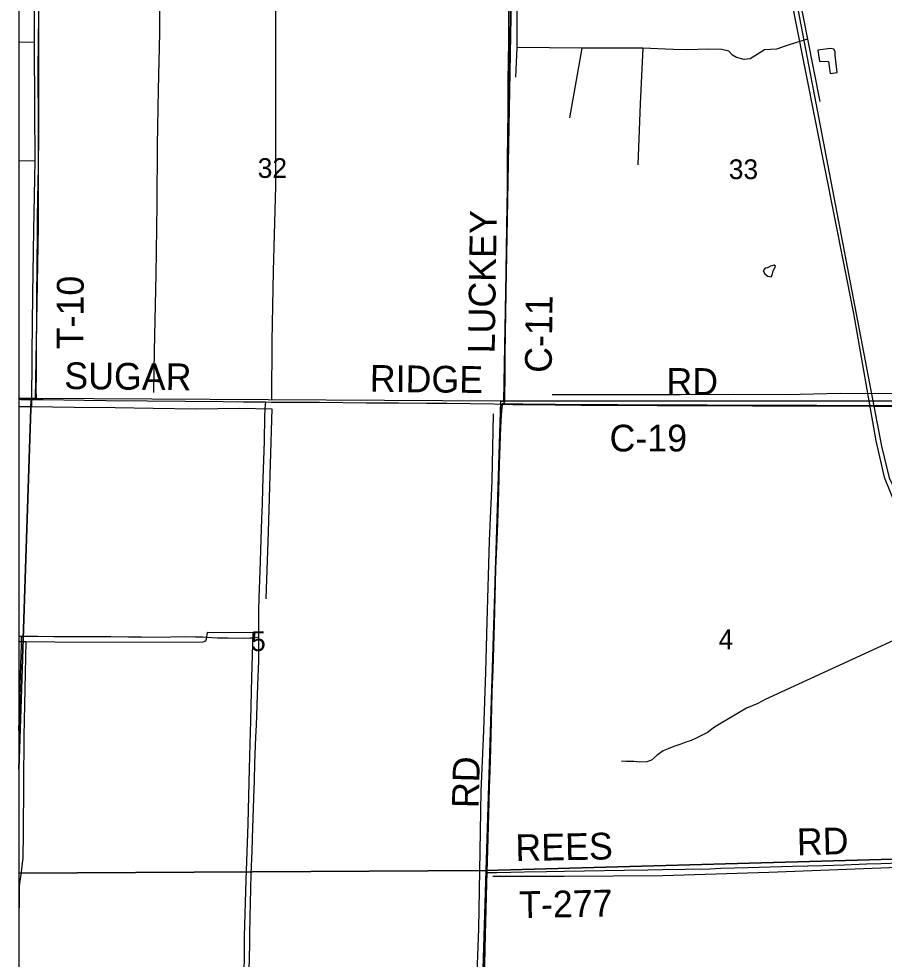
# Model space of a CAD drawing. Extents: x 0 to 34, y 0 to 22.
# Drawn here: x 2.1 to 3.939, y 17.332 to 19.331 of the extents above; entities that cross this region are included whole.
import ezdxf

# ---------------------------------------------------------------- set-up
doc = ezdxf.new("R2010")
doc.units = 0
for name, color, linetype in [('Default', 7, 'Continuous'), ('GM_X_County_Road', 7, 'Continuous'), ('GM_X_County_Road_Text', 7, 'Continuous'), ('GM_X_Minor_Lake', 7, 'Continuous'), ('GM_X_Minor_River', 7, 'Continuous'), ('GM_X_Rail_Line', 7, 'Continuous'), ('GM_X_Section', 7, 'Continuous'), ('GM_X_Section_Text', 7, 'Continuous'), ('GM_X_Township_Road', 7, 'Continuous'), ('GM_X_Township_Road_Text', 7, 'Continuous'), ('SH_Cut_Line', 7, 'Continuous'), ('SH_Data', 7, 'Continuous')]:
    doc.layers.add(name, color=color, linetype=linetype)

msp = doc.modelspace()

# ---------------------------------------------------------------- linework, layer by layer
at = {"layer": 'Default'}
for points in [[(2.1, 20.9), (2.1, 15.5125)], [(3.0884, 17.2887), (3.0911, 17.385), (3.094, 17.4937), (3.0947, 17.5172), (3.096, 17.5652), (3.0979, 17.6397), (3.0996, 17.6956), (3.1006, 17.7329), (3.102, 17.7795), (3.1045, 17.8665), (3.1053, 17.9007), (3.1069, 17.9473), (3.1096, 18.0436), (3.1115, 18.1026), (3.1131, 18.1616), (3.1153, 18.224), (3.1167, 18.2592), (3.119, 18.3263), (3.1209, 18.3853), (3.1235, 18.463), (3.1246, 18.4878), (3.1256, 18.4977), (3.1266, 18.5086), (3.1269, 18.5124), (3.1314, 18.5123), (3.1316, 18.5188), (3.1317, 18.5239), (3.1318, 18.5333), (3.1325, 18.5644), (3.1329, 18.6172), (3.1333, 18.6606), (3.1338, 18.7072), (3.1348, 18.7476), (3.1361, 18.8408), (3.1378, 18.934), (3.1381, 18.9682), (3.1383, 18.9899), (3.1386, 19.0272), (3.1391, 19.0862), (3.1395, 19.1328), (3.1398, 19.167), (3.1398, 19.1794), (3.1398, 19.198), (3.1405, 19.2415), (3.1409, 19.2819), (3.1411, 19.3192), (3.1426, 19.4466)], [(3.1426, 19.4466), (3.1411, 19.3192), (3.1409, 19.2819), (3.1405, 19.2415), (3.1398, 19.198), (3.1398, 19.1794), (3.1398, 19.167), (3.1395, 19.1328), (3.1391, 19.0862), (3.1386, 19.0272), (3.1383, 18.9899), (3.1381, 18.9682), (3.1378, 18.934), (3.1361, 18.8408), (3.1348, 18.7476), (3.1338, 18.7072), (3.1333, 18.6606), (3.1329, 18.6172), (3.1325, 18.5644), (3.1318, 18.5333), (3.1317, 18.5239), (3.1316, 18.5188), (3.1314, 18.5123), (3.1492, 18.512), (3.1709, 18.5117), (3.2393, 18.511), (3.2952, 18.5105), (3.3729, 18.5101), (3.4103, 18.5099), (3.4569, 18.5098), (3.5221, 18.5093), (3.5625, 18.5093), (3.6589, 18.5088), (3.6838, 18.5088), (3.7304, 18.5086), (3.7957, 18.5087), (3.9169, 18.5083), (3.9666, 18.5081)], [(3.9666, 18.5081), (3.9169, 18.5083), (3.7957, 18.5087), (3.7304, 18.5086), (3.6838, 18.5088), (3.6589, 18.5088), (3.5625, 18.5093), (3.5221, 18.5093), (3.4569, 18.5098), (3.4103, 18.5099), (3.3729, 18.5101), (3.2952, 18.5105), (3.2393, 18.511), (3.1709, 18.5117), (3.1492, 18.512), (3.1314, 18.5123), (3.1269, 18.5124), (3.1266, 18.5086), (3.1256, 18.4977), (3.1246, 18.4878), (3.1235, 18.463), (3.1209, 18.3853), (3.119, 18.3263), (3.1167, 18.2592), (3.1153, 18.224), (3.1131, 18.1616), (3.1115, 18.1026), (3.1096, 18.0436), (3.1069, 17.9473), (3.1053, 17.9007), (3.1045, 17.8665), (3.102, 17.7795), (3.1006, 17.7329), (3.0996, 17.6956), (3.0979, 17.6397), (3.096, 17.5652), (3.0947, 17.5172), (3.094, 17.4937), (3.0911, 17.385), (3.0884, 17.2887)]]:
    msp.add_lwpolyline(points, dxfattribs=at)
for points in [[(2.1, 19.5304), (2.1, 18.5238), (2.1261, 18.5235), (2.1356, 18.5238), (2.1418, 18.8909), (2.1432, 19.5299)], [(2.1, 18.5238), (2.1, 17.7363), (2.1261, 18.5235)], [(2.1, 17.7363), (2.1, 17.5151), (3.0931, 17.5206), (3.1239, 18.5181), (2.1356, 18.5238), (2.1261, 18.5235)], [(2.1, 17.5151), (2.1, 16.5162), (3.0627, 16.5204), (3.0931, 17.5206)]]:
    msp.add_lwpolyline(points, close=True, dxfattribs=at)
at = {"layer": 'GM_X_County_Road'}
msp.add_line((3.1271, 18.5119), (3.1317, 18.5118), dxfattribs=at)
for points in [[(3.1317, 18.5118), (3.1318, 18.5183), (3.1319, 18.5233), (3.1321, 18.5327), (3.1328, 18.5638), (3.1331, 18.6166), (3.1336, 18.6601), (3.1341, 18.7067), (3.135, 18.7471), (3.1363, 18.8403), (3.138, 18.9334), (3.1384, 18.9676), (3.1385, 18.9894), (3.1389, 19.0266), (3.1393, 19.0857), (3.1397, 19.1323), (3.14, 19.1664), (3.14, 19.1789), (3.14, 19.1975), (3.1407, 19.241), (3.1411, 19.2814), (3.1414, 19.3187), (3.1428, 19.446)], [(2.1, 18.5221), (2.1051, 18.522), (2.1377, 18.5216)], [(2.1377, 18.5216), (2.1517, 18.5215), (2.2387, 18.5204), (2.2854, 18.5199), (2.3724, 18.519), (2.4532, 18.5182), (2.534, 18.5174), (2.5775, 18.5169), (2.6246, 18.5164)], [(2.6246, 18.5164), (2.6366, 18.5162), (2.6894, 18.5159), (2.7391, 18.5157), (2.8386, 18.5149), (2.907, 18.5146), (2.966, 18.514), (3.0095, 18.5136), (3.0593, 18.513), (3.109, 18.5122), (3.1271, 18.5119)], [(3.0949, 17.5166), (3.0962, 17.5646), (3.0982, 17.6392), (3.0998, 17.6951), (3.1008, 17.7324), (3.1023, 17.7789), (3.1047, 17.8659), (3.1055, 17.9001), (3.1071, 17.9467), (3.1099, 18.043), (3.1117, 18.102), (3.1133, 18.1611), (3.1156, 18.2234), (3.1169, 18.2587), (3.1193, 18.3257), (3.1211, 18.3848), (3.1238, 18.4624), (3.1248, 18.4872), (3.1258, 18.4972), (3.1268, 18.508), (3.1271, 18.5119)], [(3.1317, 18.5118), (3.1494, 18.5114), (3.1711, 18.5111), (3.2395, 18.5105), (3.2955, 18.5099), (3.3732, 18.5095), (3.4105, 18.5094), (3.4571, 18.5092), (3.5224, 18.5088), (3.5628, 18.5088), (3.6591, 18.5083), (3.684, 18.5083), (3.7306, 18.508), (3.7959, 18.5082), (3.9171, 18.5078), (3.9668, 18.5075), (4.0166, 18.5073), (4.0694, 18.5071), (4.1077, 18.5069)], [(3.0754, 16.8694), (3.0759, 16.8781), (3.0761, 16.8812), (3.077, 16.9029), (3.0788, 16.9619), (3.0802, 17.0116), (3.0811, 17.0396), (3.0826, 17.0831), (3.0854, 17.1701), (3.0866, 17.2073), (3.0876, 17.2508), (3.0886, 17.2881), (3.0914, 17.3844), (3.0943, 17.4931), (3.0949, 17.5166)]]:
    msp.add_lwpolyline(points, dxfattribs=at)
at = {"layer": 'GM_X_Minor_Lake'}
for p, q in [((3.8237, 19.2142), (3.8385, 19.2165)), ((3.6969, 18.8048), (3.6907, 18.8016))]:
    msp.add_line(p, q, dxfattribs=at)
for points in [[(3.8385, 19.2165), (3.8345, 19.2534), (3.8343, 19.261), (3.8318, 19.2657), (3.8254, 19.2677), (3.8189, 19.2667), (3.7976, 19.2638), (3.8012, 19.2406), (3.8202, 19.2401), (3.8237, 19.2142)], [(3.6907, 18.8016), (3.6858, 18.8005), (3.6815, 18.7953), (3.6851, 18.7884), (3.6914, 18.7837), (3.6982, 18.782), (3.7009, 18.7857), (3.7027, 18.7952), (3.7055, 18.7997), (3.7075, 18.8049), (3.7049, 18.8073), (3.6969, 18.8048)]]:
    msp.add_lwpolyline(points, dxfattribs=at)
at = {"layer": 'GM_X_Minor_River'}
for p, q in [((2.1324, 19.2804), (2.1, 19.2809)), ((2.1343, 19.0279), (2.1, 19.0287))]:
    msp.add_line(p, q, dxfattribs=at)
for points in [[(2.6578, 20.6815), (2.656, 20.601), (2.6537, 20.5231), (2.6512, 20.219), (2.6493, 19.9951), (2.6476, 19.8279), (2.6469, 19.7253), (2.6465, 19.5911), (2.6447, 19.5018), (2.6453, 19.3733), (2.6453, 19.2421), (2.6451, 19.1148), (2.6457, 18.9749), (2.6405, 18.7941), (2.6378, 18.6459), (2.6366, 18.5223)], [(2.1313, 20.6274), (2.1324, 20.5586), (2.1334, 20.5247), (2.1346, 20.3962), (2.1337, 20.2974), (2.1338, 20.1791), (2.1339, 20.0248), (2.1342, 19.9031), (2.1332, 19.759), (2.1327, 19.6112), (2.1314, 19.5105), (2.1326, 19.3918), (2.1324, 19.2804), (2.133, 19.1394), (2.1343, 19.0279), (2.1309, 18.8813), (2.1293, 18.7445), (2.1276, 18.6194), (2.1267, 18.5066)], [(3.1562, 19.2065), (3.1585, 19.2698), (3.1591, 19.5062), (3.1617, 19.6268), (3.1618, 19.7687)], [(3.6916, 19.6906), (3.7229, 19.5472), (3.7486, 19.4248), (3.7755, 19.2871), (3.8021, 19.1552)], [(2.3998, 19.5107), (2.3987, 19.3005), (2.3964, 19.1797), (2.3942, 19.0623), (2.3933, 18.9361), (2.3913, 18.7875), (2.3878, 18.6253), (2.3861, 18.5364)], [(3.7755, 19.2871), (3.7522, 19.2801), (3.7324, 19.2737), (3.7095, 19.2663), (3.6844, 19.2643), (3.669, 19.2548), (3.6537, 19.2453), (3.6411, 19.2441), (3.625, 19.2486), (3.616, 19.253), (3.6082, 19.2616), (3.5939, 19.2653), (3.5663, 19.266), (3.5201, 19.2645), (3.4905, 19.2652), (3.4255, 19.2679), (3.2964, 19.2684), (3.1585, 19.2698)], [(3.2964, 19.2684), (3.2699, 19.1199)], [(3.4255, 19.2679), (3.4203, 19.1496), (3.4155, 19.02)], [(4.5878, 18.2961), (4.5922, 18.3945), (4.5929, 18.5023), (4.5939, 18.5254), (4.5899, 18.5308), (4.588, 18.5309), (4.5792, 18.53), (4.3683, 18.5298), (4.1756, 18.5314), (4.0113, 18.5335), (3.845, 18.5341), (3.7318, 18.5319), (3.6185, 18.532), (3.5049, 18.5313), (3.3887, 18.5318), (3.2334, 18.5314)], [(2.1, 18.5069), (2.1267, 18.5066), (2.2178, 18.5051), (2.3047, 18.5045), (2.3855, 18.5033), (2.4769, 18.5022), (2.5688, 18.5034), (2.6379, 18.5018), (2.6342, 18.3844), (2.6301, 18.2408), (2.6249, 18.0984)], [(3.098, 16.8233), (3.0903, 16.8196), (3.081, 16.8188), (3.0728, 16.8206), (3.0667, 16.8326), (3.0603, 16.8517), (3.0604, 16.8862), (3.0636, 16.9374), (3.0673, 17.0565), (3.071, 17.1611), (3.0721, 17.2651), (3.0773, 17.397), (3.0802, 17.5617), (3.0826, 17.6891), (3.0877, 17.8181), (3.0919, 17.9424), (3.0953, 18.0486), (3.1003, 18.2212), (3.1054, 18.3486), (3.1085, 18.4912)], [(2.5711, 16.9562), (2.5739, 17.0409), (2.5765, 17.1473), (2.5787, 17.2621), (2.5798, 17.3814), (2.5828, 17.5004), (2.587, 17.62), (2.5899, 17.7374), (2.5928, 17.84), (2.5951, 17.9312), (2.5981, 18.0258), (2.5002, 18.0267), (2.4979, 18.0123), (2.4967, 18.0085), (2.4913, 18.0064), (2.3041, 18.0053), (2.1766, 18.0059), (2.1151, 18.0065), (2.1, 18.0065)], [(3.9938, 18.0261), (3.6854, 17.8841), (3.6704, 17.8761), (3.6459, 17.8657), (3.5887, 17.8321), (3.5779, 17.8252), (3.5629, 17.8142), (3.5517, 17.8083), (3.5402, 17.8026), (3.5288, 17.7975), (3.5169, 17.7936), (3.5066, 17.7893)], [(2.1151, 18.0065), (2.1109, 17.8067), (2.1093, 17.6022), (2.1085, 17.5463), (2.1074, 17.5364), (2.105, 17.5171), (2.1008, 17.4887), (2.1009, 17.4545), (2.1, 17.4282)], [(3.5066, 17.7893), (3.4917, 17.7844), (3.4798, 17.7797), (3.4691, 17.7751), (3.4564, 17.7659), (3.444, 17.7555), (3.4345, 17.7516), (3.4197, 17.7512), (3.4064, 17.7523), (3.3909, 17.7523), (3.3807, 17.7529)], [(3.1069, 17.509), (3.2588, 17.5092), (3.4686, 17.5105), (3.6937, 17.5172), (3.9682, 17.5281), (4.1353, 17.5339), (4.2993, 17.5345), (4.4739, 17.5348)]]:
    msp.add_lwpolyline(points, dxfattribs=at)
at = {"layer": 'GM_X_Rail_Line'}
for points in [[(3.4414, 20.9), (3.5016, 20.5918), (3.7507, 19.321), (3.8733, 18.7042), (3.9207, 18.4339), (3.9385, 18.3568), (3.9629, 18.2975), (3.9974, 18.239), (4.1223, 18.078), (4.3281, 17.8226), (4.3689, 17.7633), (4.4066, 17.7097), (4.4454, 17.6387), (4.4793, 17.5709), (4.5132, 17.4611), (4.5342, 17.361), (4.5504, 17.2625), (4.562, 17.1188)], [(3.6732, 20.9), (3.6471, 20.09), (3.6471, 19.9081), (3.752, 19.3659), (3.9326, 18.4227), (3.949, 18.3555), (3.9754, 18.3001), (4.0116, 18.2329), (4.0712, 18.1586), (4.3307, 17.8397), (4.4282, 17.7343), (4.663, 17.5576), (4.8455, 17.4299), (4.9093, 17.3662)]]:
    msp.add_lwpolyline(points, dxfattribs=at)
at = {"layer": 'GM_X_Section'}
for points in [[(2.1432, 19.5299), (3.1487, 19.529), (3.1307, 18.5181), (3.1239, 18.5181), (2.1356, 18.5238), (2.1418, 18.8909)], [(4.1507, 19.5243), (4.1339, 18.5191), (4.1085, 18.519), (3.1307, 18.5181), (3.1487, 19.529)], [(3.1307, 18.5181), (4.1085, 18.519), (4.0852, 17.5486), (3.0931, 17.5206), (3.1239, 18.5181)], [(4.0852, 17.5486), (4.0656, 16.5335), (3.0627, 16.5204), (3.0931, 17.5206)]]:
    msp.add_lwpolyline(points, close=True, dxfattribs=at)
at = {"layer": 'GM_X_Township_Road'}
msp.add_line((2.1, 18.0186), (2.1061, 18.0186), dxfattribs=at)
for points in [[(2.1377, 18.5216), (2.1375, 18.5293), (2.1372, 18.5386), (2.1373, 18.576), (2.1377, 18.6319), (2.1382, 18.691), (2.1386, 18.7376), (2.1393, 18.806), (2.1399, 18.8775), (2.14, 18.9086), (2.1411, 18.9832), (2.1416, 19.0142), (2.1418, 19.0391), (2.1418, 19.0982), (2.1419, 19.1355), (2.1414, 19.1883), (2.1411, 19.2194), (2.1418, 19.2847), (2.1427, 19.3344), (2.1434, 19.3841), (2.144, 19.4432), (2.1444, 19.4836), (2.1452, 19.5337)], [(2.6099, 18.0174), (2.6097, 18.0258), (2.6097, 18.0475), (2.6102, 18.0724), (2.611, 18.1004), (2.6124, 18.1377), (2.6136, 18.1781), (2.6149, 18.2247), (2.6163, 18.2682), (2.6174, 18.2993), (2.6186, 18.3335), (2.6217, 18.4329), (2.623, 18.4858), (2.6237, 18.5013), (2.6242, 18.5106), (2.6246, 18.5164)], [(2.1, 17.8174), (2.1, 17.8178), (2.1021, 17.8862), (2.103, 17.9142), (2.105, 17.9795), (2.1059, 18.0012), (2.106, 18.0136), (2.1061, 18.0186)], [(2.1061, 18.0186), (2.1401, 18.0186), (2.1743, 18.0184), (2.2147, 18.0183), (2.2333, 18.0182), (2.2519, 18.0181), (2.2955, 18.0179), (2.3328, 18.0174), (2.3607, 18.0172), (2.3949, 18.017), (2.4229, 18.0174), (2.454, 18.0178), (2.4757, 18.0176), (2.4913, 18.0171), (2.5099, 18.0159), (2.5223, 18.0155), (2.5441, 18.0153), (2.5783, 18.0149), (2.5907, 18.015), (2.5969, 18.0154), (2.6029, 18.016), (2.6074, 18.0169), (2.6099, 18.0174)], [(2.5886, 17.2829), (2.5899, 17.3356), (2.5906, 17.365), (2.5908, 17.3855), (2.5915, 17.4228), (2.5933, 17.4819), (2.594, 17.513), (2.5957, 17.5627), (2.5973, 17.6124), (2.5979, 17.6311), (2.5994, 17.6746), (2.6005, 17.7119), (2.6017, 17.7492), (2.6039, 17.8051), (2.6048, 17.83), (2.6079, 17.9139), (2.6096, 17.9667), (2.6101, 17.9853), (2.6102, 18.004), (2.6099, 18.0174)], [(3.0949, 17.5166), (3.1165, 17.517), (3.174, 17.5179), (3.2212, 17.5188), (3.2596, 17.5196), (3.3016, 17.5204), (3.3861, 17.5216), (3.4366, 17.5223), (3.4676, 17.5228), (3.5154, 17.5236), (3.568, 17.5248), (3.5909, 17.5256), (3.6487, 17.5272), (3.6972, 17.5289), (3.7441, 17.53), (3.809, 17.5318), (3.8532, 17.5331), (3.9011, 17.5348), (3.9315, 17.5356), (4.0344, 17.5397), (4.0831, 17.5415), (4.0873, 17.5417)]]:
    msp.add_lwpolyline(points, dxfattribs=at)
at = {"layer": 'SH_Cut_Line'}
msp.add_lwpolyline([(7.1734, 20.9), (2.1, 20.9), (2.1, 14.1)], dxfattribs=at)
at = {"layer": 'SH_Data'}
msp.add_line((2.1, 20.9), (2.1, 14.1), dxfattribs=at)

# ---------------------------------------------------------------- texts
at = {"layer": 'GM_X_County_Road_Text'}
for s, rotation, p in [('LUCKEY', 89.1551, (3.111, 18.6194)), ('C-11', 89.324, (3.2321, 18.5781)), ('SUGAR', 359.3933, (2.1964, 18.544)), ('RIDGE', 359.3517, (2.8455, 18.5382)), ('RD', 0, (3.4759, 18.5315)), ('C-19', 0, (3.3551, 18.4113)), ('RD', 88.5117, (3.0769, 17.6529))]:
    msp.add_text(s, height=0.05682, rotation=rotation, dxfattribs=at).set_placement(p)
at = {"layer": 'GM_X_Section_Text'}
for s, height, p in [('32', 0.04186, (2.6076, 18.9925)), ('33', 0.04186, (3.6084, 18.99)), ('5', 0.0419, (2.5934, 17.9872)), ('4', 0.0419, (3.5867, 17.9912))]:
    msp.add_text(s, height=height, rotation=0, dxfattribs=at).set_placement(p)
at = {"layer": 'GM_X_Township_Road_Text'}
for s, rotation, p in [('T-10', 89.6467, (2.237, 18.6282)), ('RD', 1.4825, (3.7537, 17.5532)), ('REES', 1.1238, (3.1556, 17.5407)), ('T-277', 1.1131, (3.1635, 17.4197))]:
    msp.add_text(s, height=0.05682, rotation=rotation, dxfattribs=at).set_placement(p)

doc.saveas('drawing.dxf')
